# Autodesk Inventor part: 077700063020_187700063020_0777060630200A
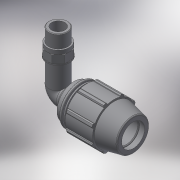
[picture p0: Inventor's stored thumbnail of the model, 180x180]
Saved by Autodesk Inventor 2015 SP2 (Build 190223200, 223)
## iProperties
Created: 2017-02
Part Number: 077700063020_187700063020_0777060630200A
Material: Generic
Description: PLASSON 90° ELBOW MALE WITH INTEGRAL BRASS THREAD 63-2"
Document SubType Name: Modeling
Designer: KIM
Mass: 174.249 g
Surface Area: 431.906 cm^2
Volume: 174.249 cm^3
Density: 1 g/cm^3
Appearance: Default
Author: KIM
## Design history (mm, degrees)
derived "07770.ipt"
feature "Solid1::07770.ipt"
tag "TaggingFeature1"
body "Solid1"
other parameters: "d2" = 63, "d4" = 14.16667, "d5" = 42.5, "d7" = 113, "d9" = 24.28571, "d11" = 5.66667, "d13" = 120 deg, "d14" = 81.9, "d15" = 12 deg, "d16" = 98.31, "d18" = 3.15, "d19" = 35 deg, "d20" = 17.5 deg, "d21" = 105.09, "d23" = 0, "d25" = 360 deg, "d27" = 2.26, "d33" = 1.26, "d42" = 62.9, "d43" = 3.39, "d46" = 1.89, "d68" = 11.33333, "d72" = 129, "d73" = 59.614, "d74" = 26, "d75" = 68.5561, "d76" = 41.7298, "d79" = 23.8456, "d80" = 1.78842, "d83" = 0, "d84" = 0, "d91" = 84.75, "d94" = 59.614, "d95" = 41.7298, "d96" = 11.33333, "d97" = 50 deg, "d98" = 2.83333, "d99" = 95.3607, "d100" = 2.83333, "d101" = 2.83333, "d105" = 2.6, "d106" = 71.5368, "d107" = 26, "d108" = 15.6, "d109" = 0, "d_" = 63, "E_" = 113, "l_2" = 26, "A_1" = 129, "R_" = 59.614
